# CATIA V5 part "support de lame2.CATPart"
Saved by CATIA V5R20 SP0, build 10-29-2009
Part number: 4
Bounding box of the stored display mesh (mm): x -57 to 7, y -25 to -15, z 15 to 65
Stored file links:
  C:\Users\halimelbaba\Documents\cmv\projet\support de lame2.CATPart
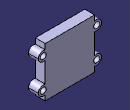
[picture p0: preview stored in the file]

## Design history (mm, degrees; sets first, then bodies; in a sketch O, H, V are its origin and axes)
Body1 (main body)
  Sketch1 on xy-plane, origin (0, 0, 0), H (1, 0, 0), V (0, 1, 0)
    line L1 (-50, 25) -> (0, 25)
    line L2 (0, 25) -> (0, -25)
    line L3 (0, -25) -> (-50, -25)
    line L4 (-50, -25) -> (-50, 25)
    distance L4 L2 = 50
    distance L3 L1 = 50
    horizontal: L1 H, L3 H
    vertical: L2 V, L4 V
    coincidence: L2 V
    symmetry: L3 L1 H
  Pad1: profile Sketch1, direction (0, 0, 1), length 15
  Plane1: type Offset, RefPlane end face of Pad1, Offset 0, reversed
  Sketch2 on end face of Pad1, origin (0, 0, 15), H (1, 0, 0), V (0, 1, 0)
    line L1 (-50, -15) -> (0, -15)
    line L2 (0, -15) -> (0, -25)
    line L3 (0, -25) -> (-50, -25)
    line L4 (-50, -25) -> (-50, -15)
    reference projected line E1 (-50, -25) -> (0, -25) from edge [face of Pad1 from Sketch1.L3 | end face of Pad1]
    reference projected line E2 (0, -25) -> (0, 25) from edge [face of Pad1 from Sketch1.L2 | end face of Pad1]
    reference projected line E3 (-50, 25) -> (-50, -25) from edge [face of Pad1 from Sketch1.L4 | end face of Pad1]
    distance L1 L3 = 10
    horizontal: L1 H, L3 H
    vertical: L2 V, L4 V
    coincidence: L3 E1, L2 E2, L4 E3
  Pad2: profile Sketch2, direction (0, 0, 1), length 50
  Plane2: type Offset, RefPlane face of Pad2, Offset 0, reversed
  Sketch3 on face of Pad2, origin (0, -25, 0), H (1, 0, 0), V (0, 0, 1)
    circle A1 centre (2, 55) radius 5
    point P1 (2, 55)
    reference projected line E1 (0, 0) -> (0, 15) from edge [face of Pad2 | face of Pad2]
    reference projected line E2 (-50, 65) -> (0, 65) from edge [face of Pad2 | end face of Pad2]
    circle A2 centre (-52, 55) radius 5
    point P2 (-52, 55)
    reference projected line E3 (-50, 65) -> (0, 65) from edge [face of Pad2 | end face of Pad2]
    reference projected line E4 (-50, 0) -> (-50, 15) from edge [face of Pad2 | face of Pad2]
    point P3 (-44.3226, 0)
    circle A3 centre (-52, 25) radius 5
    point P4 (-52, 25)
    reference projected line E5 (-50, 0) -> (-50, 15) from edge [face of Pad2 | face of Pad2]
    reference projected line E6 (-50, 0) -> (0, 0) from edge [start face of Pad1 | face of Pad2]
    circle A4 centre (2, 25) radius 5
    point P5 (2, 25)
    reference projected line E7 (-50, 0) -> (0, 0) from edge [start face of Pad1 | face of Pad2]
    reference projected line E8 (0, 0) -> (0, 15) from edge [face of Pad2 | face of Pad2]
    distance P1 E1 = 2
    distance P1 E2 = 10
    radius A1 = 5
    distance P2 E3 = 10
    distance P2 E4 = 2
    radius A2 = 5
    distance P4 E5 = 2
    radius A3 = 5
    distance P4 E6 = 25
    distance P5 E7 = 25
    radius A4 = 5
    distance P5 E8 = 2
    coincidence: P3 H
  Pad3: profile Sketch3, direction (0, 1, 0), up to face of Pad2 from Sketch2.L1
  Sketch4 on face of Pad2, origin (-7.5024, -25, 54.4561), H (1, 0, 0), V (0, 0, 1)
    point P1 (9.5024, 0.5439)
    reference projected circle E1 centre (9.5024, 0.5439) radius 5 from edge [face of Pad3 from Sketch3.A1 | face of Pad2]
    concentricity: P1 E1
  Hole1: placed by Sketch4, at (2, -25, 55) direction (0, 1, 0), diameter 6, up to face of Pad2
  Sketch5 on face of Pad2, origin (3.3216, -25, 26.4177), H (1, 0, 0), V (0, 0, 1)
    point P1 (-1.3216, -1.4177)
    reference projected circle E1 centre (-1.3216, -1.4177) radius 5 from edge [face of Pad3 from Sketch3.A4 | face of Pad2]
    concentricity: P1 E1
  Hole2: placed by Sketch5, at (2, -25, 25) direction (0, 1, 0), diameter 6, up to face of Pad2
  Sketch6 on face of Pad2, origin (-27.6498, -25, 45.543), H (1, 0, 0), V (0, 0, 1)
    point P1 (-24.3502, 9.457)
    reference projected circle E1 centre (-24.3502, 9.457) radius 5 from edge [face of Pad3 from Sketch3.A2 | face of Pad2]
    concentricity: P1 E1
  Hole3: placed by Sketch6, at (-52, -25, 55) direction (0, 1, 0), diameter 6, up to face of Pad2
  Sketch7 on face of Pad2, origin (-44.0968, -25, 29.5826), H (1, 0, 0), V (0, 0, 1)
    point P1 (-7.9032, -4.5826)
    reference projected circle E1 centre (-7.9032, -4.5826) radius 5 from edge [face of Pad3 from Sketch3.A3 | face of Pad2]
    concentricity: P1 E1
  Hole4: placed by Sketch7, at (-52, -25, 25) direction (0, 1, 0), diameter 6, up to face of Pad2
  Sketch8 on end face of Pad1, origin (-41.3366, 10.9957, 15), H (1, 0, 0), V (0, 1, 0)
    point P1 (1.3366, -0.9957)
    reference projected line E1 (41.3366, 14.0043) -> (-8.6634, 14.0043) from edge [face of Pad1 from Sketch1.L1 | end face of Pad1]
    reference projected line E2 (-8.6634, 14.0043) -> (-8.6634, -35.9957) from edge [face of Pad2 | end face of Pad1]
    distance P1 E1 = 15
    distance P1 E2 = 10
  Hole5: placed by Sketch8, at (-40, 10, 15) direction (0, 0, -1), diameter 10, up to start face of Pad1
  Sketch9 on end face of Pad1, origin (-18.7285, 9.4346, 15), H (1, 0, 0), V (0, 1, 0)
    point P1 (8.7285, 0.5654)
    reference projected line E1 (18.7285, -34.4346) -> (18.7285, 15.5654) from edge [face of Pad2 | end face of Pad1]
    reference projected line E2 (18.7285, 15.5654) -> (-31.2715, 15.5654) from edge [face of Pad1 from Sketch1.L1 | end face of Pad1]
    distance P1 E1 = 10
    distance P1 E2 = 15
  Hole6: placed by Sketch9, at (-10, 10, 15) direction (0, 0, -1), diameter 10, up to start face of Pad1
  Sketch10 on end face of Pad1, origin (-25.1212, 7.5024, 15), H (1, 0, 0), V (0, 1, 0)
    point P1 (15.1212, 2.4976)
    reference projected circle E1 centre (15.1212, 2.4976) radius 5 from edge [end face of Pad1 | face of Hole6]
    concentricity: P1 E1
  Hole7: placed by Sketch10, at (-10, 10, 15) direction (0, 0, -1), diameter 14, depth 4
  Sketch11 on end face of Pad1, origin (-30.6696, 3.3789, 15), H (1, 0, 0), V (0, 1, 0)
    point P1 (-9.3304, 6.6211)
    reference projected circle E1 centre (-9.3304, 6.6211) radius 5 from edge [end face of Pad1 | face of Hole5]
    reference projected circle E2 centre (-9.3304, 6.6211) radius 5 from edge [end face of Pad1 | face of Hole5]
    concentricity: E1 P1, P1 E2
  Hole8: placed by Sketch11, at (-40, 10, 15) direction (0, 0, -1), diameter 14, depth 4
  Plane3: type Offset, RefPlane face of Pad1 from Sketch1.L1, Offset 0, reversed
  Sketch12 on Plane3, origin (0, 25, 0), H (1, 0, 0), V (0, 0, 1)
    line L1 (0, 15) -> (-50, 15)
    line L2 (-50, 15) -> (-50, 0)
    line L3 (-50, 0) -> (0, 0)
    line L4 (0, 0) -> (0, 15)
    reference projected line E1 (0, 15) -> (-50, 15) from edge [face of Pad1 from Sketch1.L1 | end face of Pad1]
    reference projected line E2 (-50, 0) -> (-50, 15) from edge [face of Pad1 from Sketch1.L4 | face of Pad1 from Sketch1.L1]
    reference projected line E3 (0, 0) -> (-50, 0) from edge [start face of Pad1 | face of Pad1 from Sketch1.L1]
    horizontal: L1 H, L3 H
    vertical: L2 V, L4 V
    coincidence: L1 E1, L2 E2, L3 E3, L4 V
  Pocket1: profile Sketch12, direction (0, -1, 0), up to face of Pad2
